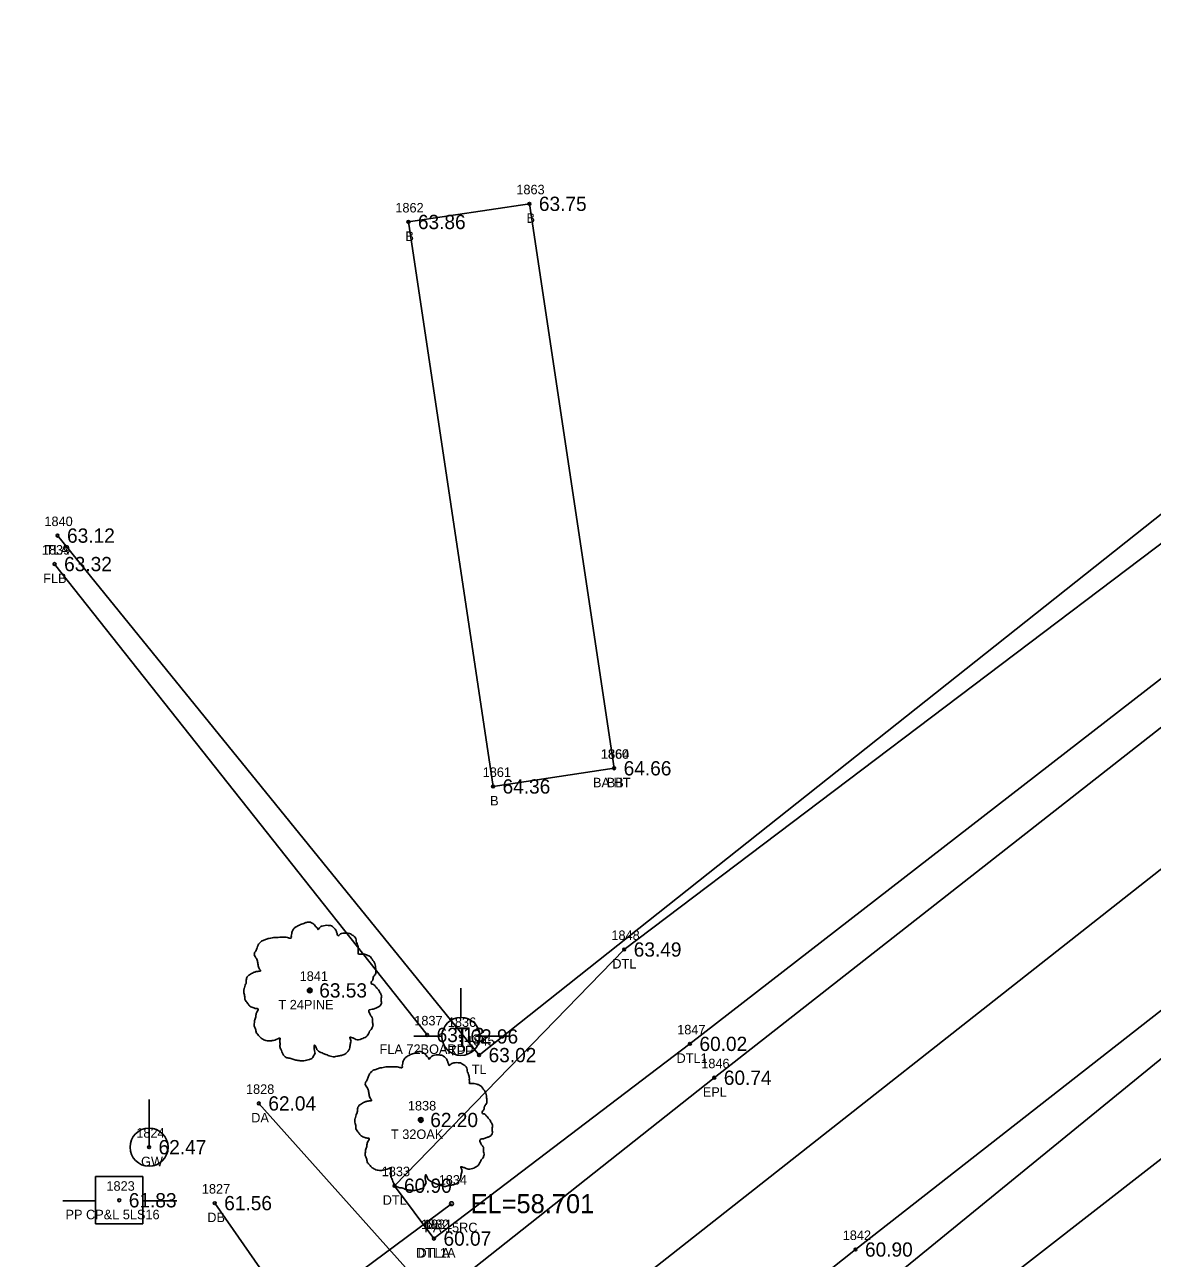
# Model space of a CAD drawing. Extents: x 2420113 to 2422887, y 845323 to 846653.
# Drawn here: x 2422429.8 to 2422548.3, y 846359.2 to 846488.9 of the extents above; entities that cross this region are included whole.
import ezdxf

# ---------------------------------------------------------------- set-up
doc = ezdxf.new("R2010")
doc.units = 0
for name, color, linetype in [('RD_EX_Bldg', 7, 'Continuous'), ('RD_EX_Bldg_txCode', 7, 'Continuous'), ('RD_EX_DR_Pipe', 7, 'Continuous'), ('RD_EX_DR_Pipe_txCode', 7, 'Continuous'), ('RD_EX_Driveway', 7, 'Continuous'), ('RD_EX_Driveway_txCode', 7, 'Continuous'), ('RD_EX_Fence_Other', 7, 'Continuous'), ('RD_EX_Fence_Other_txCode', 7, 'Continuous'), ('RD_EX_H2O', 7, 'Continuous'), ('RD_EX_H2O_txCode', 7, 'Continuous'), ('RD_EX_Road', 7, 'Continuous'), ('RD_EX_Road_txCode', 7, 'Continuous'), ('RD_EX_TX_Bldg_ELEV', 7, 'Continuous'), ('RD_EX_TX_Driveway_ELEV', 7, 'Continuous'), ('RD_EX_TX_Fence_Other_ELEV', 7, 'Continuous'), ('RD_EX_TX_H2O_ELEV', 7, 'Continuous'), ('RD_EX_TX_Road_ELEV', 7, 'Continuous'), ('RD_EX_TX_UT_ELEV', 7, 'Continuous'), ('RD_EX_TX_VEG_ELEV', 7, 'Continuous'), ('RD_EX_UT', 7, 'Continuous'), ('RD_EX_UT_txCode', 7, 'Continuous'), ('RD_EX_VEG', 7, 'Continuous'), ('RD_EX_VEG_txCode', 7, 'Continuous'), ('RD_HC_Cl', 7, 'Continuous'), ('RD_HC_Survey_ELEV', 7, 'Continuous'), ('RD_SMD_Locator', 7, 'Continuous'), ('RD_TX_Pipe_ElevEX', 7, 'Continuous')]:
    doc.layers.add(name, color=color, linetype=linetype)

msp = doc.modelspace()

# ---------------------------------------------------------------- linework, layer by layer
at = {"layer": 'RD_EX_Bldg'}
msp.add_lwpolyline([(2422491.77, 846410.69), (2422479.04, 846408.78), (2422470.14, 846468.12), (2422482.86, 846470.03), (2422491.77, 846410.69)], dxfattribs=at)
at = {"layer": 'RD_EX_DR_Pipe'}
msp.add_line((2422474.67, 846364.92), (2422454.62, 846350.03), dxfattribs=at)
at = {"layer": 'RD_EX_Driveway'}
for p, q in [((2422454.42, 846375.46), (2422472.85, 846354.85)), ((2422462.49, 846346.77), (2422449.78, 846364.98))]:
    msp.add_line(p, q, dxfattribs=at)
at = {"layer": 'RD_EX_Fence_Other'}
msp.add_line((2422472.11, 846382.66), (2422432.95, 846432.16), dxfattribs=at)
at = {"layer": 'RD_EX_H2O'}
for points in [[(2422472.83, 846361.25), (2422468.68, 846366.81), (2422492.83, 846391.64), (2422569.21, 846449.39), (2422595.74, 846472)], [(2422472.83, 846361.25), (2422499.74, 846381.72), (2422575.73, 846440.62), (2422602, 846462.6), (2422600.58, 846468.4), (2422595.74, 846472)], [(2422383.12, 846248.84), (2422451.79, 846302.96), (2422519.84, 846356.14), (2422594.22, 846416.85), (2422660.96, 846466.59)], [(2422383.12, 846248.84), (2422386.53, 846244.46), (2422456.45, 846298.4), (2422524.56, 846350.4), (2422601.29, 846410.12), (2422664.82, 846461.69)]]:
    msp.add_lwpolyline(points, dxfattribs=at)
at = {"layer": 'RD_EX_Road'}
for points in [[(2421810.77, 845819.82), (2421809.69, 845832.82), (2421803.88, 845842.86), (2421852.96, 845873.69), (2421939.48, 845935.12), (2421980.78, 845967.01), (2422140.12, 846092.81), (2422210.03, 846148.43), (2422282.88, 846205.21), (2422291.79, 846212.09), (2422354.49, 846261.98), (2422400.82, 846297.88), (2422417.34, 846311.65), (2422435.4, 846324.77), (2422462.49, 846346.77), (2422472.85, 846354.85), (2422502.3, 846378.16), (2422578.05, 846437.54), (2422605.64, 846459.09), (2422626.64, 846476.17), (2422642.61, 846488.86)], [(2421810.77, 845819.82), (2421865.31, 845853.52), (2421953.26, 845916.07), (2421995.06, 845948.03), (2422068.36, 846005.98), (2422153.46, 846073.36), (2422229.55, 846134.03), (2422245.4, 846145.63), (2422297.08, 846186.88), (2422369.77, 846243.69), (2422382.04, 846253.08), (2422449.02, 846305.97), (2422517.14, 846360.1), (2422592.58, 846419.1), (2422657.51, 846470.1)]]:
    msp.add_lwpolyline(points, dxfattribs=at)
at = {"layer": 'RD_EX_UT'}
for p, q in [((2422475.66, 846387.57), (2422475.66, 846384.5)), ((2422470.73, 846382.52), (2422473.66, 846382.52)), ((2422477.66, 846382.52), (2422480.73, 846382.52)), ((2422442.88, 846370.86), (2422442.88, 846375.86)), ((2422442.24, 846367.79), (2422437.24, 846367.79)), ((2422437.24, 846367.79), (2422437.24, 846362.79)), ((2422442.24, 846362.79), (2422442.24, 846367.79)), ((2422433.81, 846365.23), (2422437.28, 846365.23)), ((2422442.17, 846365.23), (2422445.81, 846365.23)), ((2422437.24, 846362.79), (2422442.24, 846362.79))]:
    msp.add_line(p, q, dxfattribs=at)
for centre in [(2422475.66, 846382.5), (2422442.88, 846370.86)]:
    msp.add_circle(centre, 2, dxfattribs=at)
at = {"layer": 'RD_EX_VEG'}
msp.add_lwpolyline([(2422433.26, 846435.15), (2422477.57, 846380.54), (2422567.43, 846451.81), (2422594.81, 846473.94), (2422582.02, 846486.76)], dxfattribs=at)
for centre, radius in [((2422459.77, 846387.34), 0.25), ((2422459.76, 846387.32), 0.0001), ((2422471.44, 846373.72), 0.25), ((2422471.43, 846373.7), 0.0001)]:
    msp.add_circle(centre, radius, dxfattribs=at)
for points in [[(2422459.9, 846394.51), (2422459.6, 846394.53), (2422459.28, 846394.43), (2422459.03, 846394.33), (2422458.8, 846394.26), (2422458.58, 846394.16), (2422458.28, 846393.98), (2422458.05, 846393.78), (2422457.93, 846393.53), (2422457.88, 846393.31), (2422457.83, 846393.03), (2422457.83, 846392.86), (2422457.7, 846392.83), (2422457.55, 846392.86), (2422457.3, 846392.93), (2422457.05, 846392.93), (2422456.8, 846392.93), (2422456.45, 846392.91), (2422456.1, 846392.91), (2422455.83, 846392.86), (2422455.5, 846392.81), (2422455.13, 846392.68), (2422454.78, 846392.56), (2422454.48, 846392.31), (2422454.23, 846391.83), (2422454.1, 846391.48), (2422453.95, 846391.23), (2422454.1, 846390.78), (2422454.28, 846390.43), (2422454.3, 846390.23), (2422454.38, 846389.81), (2422454.48, 846389.58), (2422454.6, 846389.38), (2422454.53, 846389.36), (2422454.15, 846389.31), (2422453.85, 846389.21), (2422453.43, 846388.98), (2422453.2, 846388.76), (2422453.1, 846388.43), (2422453.08, 846388.08), (2422452.98, 846387.88), (2422452.9, 846387.61), (2422452.88, 846387.53), (2422452.83, 846387.21), (2422452.93, 846386.76), (2422452.95, 846386.41), (2422453.08, 846386.18), (2422453.23, 846386.01), (2422453.4, 846385.76), (2422453.8, 846385.53), (2422454.13, 846385.43), (2422454.33, 846385.41), (2422454.15, 846384.91), (2422454.1, 846384.56), (2422453.98, 846384.16), (2422453.98, 846384.08), (2422453.93, 846383.61), (2422454.08, 846383.28), (2422454.15, 846382.91), (2422454.33, 846382.69), (2422454.6, 846382.39), (2422454.93, 846382.16), (2422455.43, 846382.04), (2422455.83, 846382.06), (2422456.4, 846382.24), (2422456.65, 846382.31), (2422456.63, 846382.14), (2422456.65, 846381.76), (2422456.65, 846381.34), (2422456.8, 846381.01), (2422456.9, 846380.74), (2422457.05, 846380.49), (2422457.38, 846380.26), (2422457.78, 846380.19), (2422458.2, 846380.04), (2422458.65, 846379.96), (2422459.15, 846379.94), (2422459.75, 846380.09), (2422460.03, 846380.21), (2422460.13, 846380.39), (2422460.33, 846380.76), (2422460.28, 846380.99), (2422460.3, 846381.59), (2422460.4, 846381.41), (2422460.58, 846381.06), (2422461.08, 846380.76), (2422461.47, 846380.59), (2422461.95, 846380.44), (2422462.25, 846380.36), (2422462.72, 846380.44), (2422463.1, 846380.51), (2422463.47, 846380.64), (2422463.77, 846380.91), (2422463.95, 846381.19), (2422464, 846381.46), (2422464.07, 846381.84), (2422464.12, 846382.01)], [(2422464.12, 846382.01), (2422464.05, 846382.19), (2422464, 846382.44), (2422464.07, 846382.41), (2422464.25, 846382.36), (2422464.52, 846382.24), (2422464.75, 846382.16), (2422465.07, 846382.19), (2422465.35, 846382.29), (2422465.8, 846382.56), (2422466.07, 846383.04), (2422466.35, 846383.43), (2422466.42, 846383.76), (2422466.37, 846383.98), (2422466.35, 846384.48), (2422466.15, 846384.73), (2422466.1, 846384.86), (2422466, 846385.26), (2422466.07, 846385.31), (2422466.35, 846385.36), (2422466.72, 846385.48), (2422467, 846385.61), (2422467.22, 846385.78), (2422467.3, 846386.01), (2422467.27, 846386.41), (2422467.32, 846386.81), (2422467.25, 846386.96), (2422467.15, 846387.11), (2422467.07, 846387.31), (2422466.92, 846387.46), (2422466.82, 846387.61), (2422466.72, 846387.71), (2422466.6, 846387.86), (2422466.42, 846387.98), (2422466.27, 846388.03), (2422466.22, 846388.18), (2422466.37, 846388.38), (2422466.42, 846388.48), (2422466.45, 846388.71), (2422466.67, 846389.06), (2422466.72, 846389.46), (2422466.67, 846389.88), (2422466.62, 846390.16), (2422466.47, 846390.43), (2422466.27, 846390.68), (2422466.15, 846390.86), (2422465.97, 846390.98), (2422465.65, 846391.11), (2422465.4, 846391.16), (2422465.05, 846391.16), (2422464.85, 846391.21), (2422464.87, 846391.26), (2422464.87, 846391.41), (2422464.87, 846391.68), (2422464.8, 846392.13), (2422464.65, 846392.63), (2422464.65, 846392.66), (2422464.55, 846392.91), (2422464.32, 846393.11), (2422464.15, 846393.21), (2422463.95, 846393.33), (2422463.7, 846393.36), (2422463.4, 846393.36), (2422463.12, 846393.31), (2422462.92, 846393.21), (2422462.75, 846393.08), (2422462.67, 846393.23), (2422462.57, 846393.53), (2422462.52, 846393.68), (2422462.37, 846393.86), (2422462.15, 846394.06), (2422461.7, 846394.18), (2422461.08, 846394.11), (2422460.78, 846393.91), (2422460.63, 846393.73), (2422460.58, 846393.86), (2422460.38, 846394.06), (2422460.28, 846394.23), (2422460.1, 846394.36), (2422459.95, 846394.46), (2422459.85, 846394.51)], [(2422471.57, 846380.89), (2422471.27, 846380.91), (2422470.95, 846380.81), (2422470.7, 846380.71), (2422470.47, 846380.64), (2422470.25, 846380.54), (2422469.95, 846380.36), (2422469.72, 846380.16), (2422469.6, 846379.91), (2422469.55, 846379.69), (2422469.5, 846379.41), (2422469.5, 846379.24), (2422469.37, 846379.21), (2422469.22, 846379.24), (2422468.97, 846379.31), (2422468.72, 846379.31), (2422468.47, 846379.31), (2422468.12, 846379.29), (2422467.77, 846379.29), (2422467.5, 846379.24), (2422467.17, 846379.19), (2422466.8, 846379.06), (2422466.45, 846378.94), (2422466.15, 846378.69), (2422465.9, 846378.21), (2422465.77, 846377.86), (2422465.62, 846377.61), (2422465.77, 846377.16), (2422465.95, 846376.81), (2422465.97, 846376.61), (2422466.05, 846376.19), (2422466.15, 846375.96), (2422466.27, 846375.76), (2422466.2, 846375.74), (2422465.82, 846375.69), (2422465.52, 846375.59), (2422465.1, 846375.36), (2422464.88, 846375.14), (2422464.78, 846374.81), (2422464.75, 846374.46), (2422464.65, 846374.26), (2422464.58, 846373.99), (2422464.55, 846373.91), (2422464.5, 846373.59), (2422464.6, 846373.14), (2422464.63, 846372.79), (2422464.75, 846372.57), (2422464.9, 846372.39), (2422465.08, 846372.14), (2422465.47, 846371.92), (2422465.8, 846371.82), (2422466, 846371.79), (2422465.82, 846371.29), (2422465.77, 846370.94), (2422465.65, 846370.54), (2422465.65, 846370.47), (2422465.6, 846369.99), (2422465.75, 846369.67), (2422465.82, 846369.29), (2422466, 846369.07), (2422466.27, 846368.77), (2422466.6, 846368.54), (2422467.1, 846368.42), (2422467.5, 846368.44), (2422468.07, 846368.62), (2422468.32, 846368.69), (2422468.3, 846368.52), (2422468.32, 846368.14), (2422468.32, 846367.72), (2422468.47, 846367.39), (2422468.57, 846367.12), (2422468.72, 846366.87), (2422469.05, 846366.64), (2422469.45, 846366.57), (2422469.87, 846366.42), (2422470.32, 846366.34), (2422470.82, 846366.32), (2422471.42, 846366.47), (2422471.7, 846366.59), (2422471.8, 846366.77), (2422472, 846367.14), (2422471.95, 846367.37), (2422471.97, 846367.97), (2422472.07, 846367.79), (2422472.25, 846367.44), (2422472.75, 846367.14), (2422473.15, 846366.97), (2422473.62, 846366.82), (2422473.92, 846366.74), (2422474.4, 846366.82), (2422474.77, 846366.89), (2422475.15, 846367.02), (2422475.45, 846367.29), (2422475.62, 846367.57), (2422475.67, 846367.84), (2422475.75, 846368.22), (2422475.8, 846368.39)], [(2422475.8, 846368.39), (2422475.72, 846368.57), (2422475.67, 846368.82), (2422475.75, 846368.79), (2422475.92, 846368.74), (2422476.2, 846368.62), (2422476.42, 846368.54), (2422476.74, 846368.57), (2422477.02, 846368.67), (2422477.47, 846368.94), (2422477.74, 846369.42), (2422478.02, 846369.82), (2422478.09, 846370.14), (2422478.04, 846370.37), (2422478.02, 846370.87), (2422477.82, 846371.12), (2422477.77, 846371.24), (2422477.67, 846371.64), (2422477.74, 846371.69), (2422478.02, 846371.74), (2422478.39, 846371.87), (2422478.67, 846371.99), (2422478.89, 846372.17), (2422478.97, 846372.39), (2422478.94, 846372.79), (2422478.99, 846373.19), (2422478.92, 846373.34), (2422478.82, 846373.49), (2422478.74, 846373.69), (2422478.59, 846373.84), (2422478.49, 846373.99), (2422478.39, 846374.09), (2422478.27, 846374.24), (2422478.09, 846374.36), (2422477.94, 846374.41), (2422477.89, 846374.56), (2422478.04, 846374.76), (2422478.09, 846374.86), (2422478.12, 846375.09), (2422478.34, 846375.44), (2422478.39, 846375.84), (2422478.34, 846376.26), (2422478.29, 846376.54), (2422478.14, 846376.81), (2422477.94, 846377.06), (2422477.82, 846377.24), (2422477.64, 846377.36), (2422477.32, 846377.49), (2422477.07, 846377.54), (2422476.72, 846377.54), (2422476.52, 846377.59), (2422476.55, 846377.64), (2422476.55, 846377.79), (2422476.55, 846378.06), (2422476.47, 846378.51), (2422476.32, 846379.01), (2422476.32, 846379.04), (2422476.22, 846379.29), (2422476, 846379.49), (2422475.82, 846379.59), (2422475.62, 846379.71), (2422475.37, 846379.74), (2422475.07, 846379.74), (2422474.8, 846379.69), (2422474.6, 846379.59), (2422474.42, 846379.46), (2422474.35, 846379.61), (2422474.25, 846379.91), (2422474.2, 846380.06), (2422474.05, 846380.24), (2422473.82, 846380.44), (2422473.37, 846380.56), (2422472.75, 846380.49), (2422472.45, 846380.29), (2422472.3, 846380.11), (2422472.25, 846380.24), (2422472.05, 846380.44), (2422471.95, 846380.61), (2422471.77, 846380.74), (2422471.62, 846380.84), (2422471.52, 846380.89)]]:
    msp.add_spline(points, degree=3, dxfattribs=at)
at = {"layer": 'RD_HC_Cl'}
msp.add_line((2421944.32, 845923.85), (2422642.7, 846473.66), dxfattribs=at)
at = {"layer": 'RD_SMD_Locator'}
for centre, radius in [((2422482.86, 846470.03), 0.15), ((2422470.14, 846468.12), 0.15), ((2422433.26, 846435.15), 0.15), ((2422432.95, 846432.16), 0.15), ((2422491.77, 846410.69), 0.15), ((2422491.77, 846410.69), 0.15), ((2422479.04, 846408.78), 0.15), ((2422492.83, 846391.64), 0.15), ((2422459.77, 846387.34), 0.15), ((2422472.11, 846382.66), 0.15), ((2422475.66, 846382.5), 0.15), ((2422499.74, 846381.72), 0.15), ((2422477.57, 846380.54), 0.15), ((2422502.3, 846378.16), 0.15), ((2422454.42, 846375.46), 0.15), ((2422471.44, 846373.72), 0.15), ((2422442.88, 846370.86), 0.15), ((2422468.68, 846366.81), 0.15), ((2422439.75, 846365.28), 0.15), ((2422449.78, 846364.98), 0.15), ((2422474.67, 846364.92), 0.2), ((2422472.83, 846361.25), 0.15), ((2422472.83, 846361.25), 0.15), ((2422517.14, 846360.1), 0.15)]:
    msp.add_circle(centre, radius, dxfattribs=at)

# ---------------------------------------------------------------- texts
at = {"layer": 'RD_EX_Bldg_txCode'}
for s, p in [('1863', (2422481.49, 846471.03)), ('1862', (2422468.77, 846469.12)), ('B', (2422482.56, 846468.03)), ('B', (2422469.83, 846466.12)), ('1860', (2422490.36, 846411.69)), ('1864', (2422490.4, 846411.69)), ('1861', (2422477.95, 846409.78)), ('BA HT', (2422489.55, 846408.69)), ('BB', (2422490.99, 846408.69)), ('B', (2422478.73, 846406.78))]:
    msp.add_text(s, height=1, dxfattribs=at).set_placement(p)
at = {"layer": 'RD_EX_DR_Pipe_txCode'}
for s, p in [('1834', (2422473.33, 846366.92)), ('PA 15RC', (2422471.83, 846361.92))]:
    msp.add_text(s, height=1, dxfattribs=at).set_placement(p)
at = {"layer": 'RD_EX_Driveway_txCode'}
for s, p in [('1828', (2422453.07, 846376.46)), ('DA', (2422453.62, 846373.46)), ('1827', (2422448.43, 846365.98)), ('DB', (2422449, 846362.98))]:
    msp.add_text(s, height=1, dxfattribs=at).set_placement(p)
at = {"layer": 'RD_EX_Fence_Other_txCode'}
for s, p in [('1839', (2422431.61, 846433.16)), ('FLB', (2422431.75, 846430.16)), ('1837', (2422470.76, 846383.66)), ('FLA 72BOARD', (2422467.11, 846380.66))]:
    msp.add_text(s, height=1, dxfattribs=at).set_placement(p)
at = {"layer": 'RD_EX_H2O_txCode'}
for s, p in [('1848', (2422491.48, 846392.64)), ('DTL', (2422491.58, 846389.64)), ('1847', (2422498.4, 846382.72)), ('DTL1', (2422498.33, 846379.72)), ('1833', (2422467.34, 846367.81)), ('DTL', (2422467.44, 846364.81)), ('1832', (2422471.48, 846362.25)), ('1831', (2422471.77, 846362.25)), ('DTL1A', (2422470.93, 846359.25)), ('DTLA', (2422471.1, 846359.25))]:
    msp.add_text(s, height=1, dxfattribs=at).set_placement(p)
at = {"layer": 'RD_EX_Road_txCode'}
for s, p in [('1846', (2422500.93, 846379.16)), ('EPL', (2422501.09, 846376.16)), ('1842', (2422515.8, 846361.1))]:
    msp.add_text(s, height=1, dxfattribs=at).set_placement(p)
at = {"layer": 'RD_EX_TX_Bldg_ELEV'}
for s, p in [('63.75', (2422483.86, 846469.28)), ('63.86', (2422471.14, 846467.37)), ('64.66', (2422492.77, 846409.94)), ('64.66', (2422492.77, 846409.94)), ('64.36', (2422480.04, 846408.03))]:
    msp.add_text(s, height=1.5, dxfattribs=at).set_placement(p)
at = {"layer": 'RD_EX_TX_Driveway_ELEV'}
for s, p in [('62.04', (2422455.42, 846374.71)), ('61.56', (2422450.78, 846364.23))]:
    msp.add_text(s, height=1.5, dxfattribs=at).set_placement(p)
at = {"layer": 'RD_EX_TX_Fence_Other_ELEV'}
for s, p in [('63.32', (2422433.95, 846431.41)), ('63.13', (2422473.11, 846381.91))]:
    msp.add_text(s, height=1.5, dxfattribs=at).set_placement(p)
at = {"layer": 'RD_EX_TX_H2O_ELEV'}
for s, p in [('63.49', (2422493.83, 846390.89)), ('60.02', (2422500.74, 846380.97)), ('60.90', (2422469.68, 846366.06)), ('60.07', (2422473.83, 846360.5)), ('60.07', (2422473.83, 846360.5))]:
    msp.add_text(s, height=1.5, dxfattribs=at).set_placement(p)
at = {"layer": 'RD_EX_TX_Road_ELEV'}
for s, p in [('60.74', (2422503.3, 846377.41)), ('60.90', (2422518.14, 846359.35))]:
    msp.add_text(s, height=1.5, dxfattribs=at).set_placement(p)
at = {"layer": 'RD_EX_TX_UT_ELEV'}
for s, p in [('62.96', (2422476.66, 846381.75)), ('62.47', (2422443.88, 846370.11))]:
    msp.add_text(s, height=1.5, dxfattribs=at).set_placement(p)
at = {"layer": 'RD_EX_TX_VEG_ELEV'}
for s, p in [('63.12', (2422434.26, 846434.4)), ('63.53', (2422460.77, 846386.59)), ('63.02', (2422478.57, 846379.79)), ('62.20', (2422472.44, 846372.97))]:
    msp.add_text(s, height=1.5, dxfattribs=at).set_placement(p)
at = {"layer": 'RD_EX_UT'}
msp.add_text('T', height=2, dxfattribs=at).set_placement((2422474.99, 846381.46))
at = {"layer": 'RD_EX_UT_txCode'}
for s, p in [('1836', (2422474.29, 846383.5)), ('TPP', (2422474.39, 846380.5)), ('1824', (2422441.54, 846371.86)), ('GW', (2422442.04, 846368.86)), ('1823', (2422438.4, 846366.28)), ('PP CP&L 5LS16', (2422434.1, 846363.28))]:
    msp.add_text(s, height=1, dxfattribs=at).set_placement(p)
at = {"layer": 'RD_EX_VEG_txCode'}
for s, p in [('1840', (2422431.88, 846436.15)), ('TLA', (2422432, 846433.15)), ('1841', (2422458.71, 846388.34)), ('T 24PINE', (2422456.48, 846385.34)), ('1845', (2422476.23, 846381.54)), ('TL', (2422476.8, 846378.54)), ('1838', (2422470.09, 846374.72)), ('T 32OAK', (2422468.31, 846371.72))]:
    msp.add_text(s, height=1, dxfattribs=at).set_placement(p)
at = {"layer": 'RD_HC_Survey_ELEV'}
msp.add_text('61.83', height=1.5, dxfattribs=at).set_placement((2422440.75, 846364.53))
at = {"layer": 'RD_TX_Pipe_ElevEX'}
msp.add_text('EL=58.701', height=2, dxfattribs=at).set_placement((2422476.67, 846363.92))

doc.saveas('drawing.dxf')
